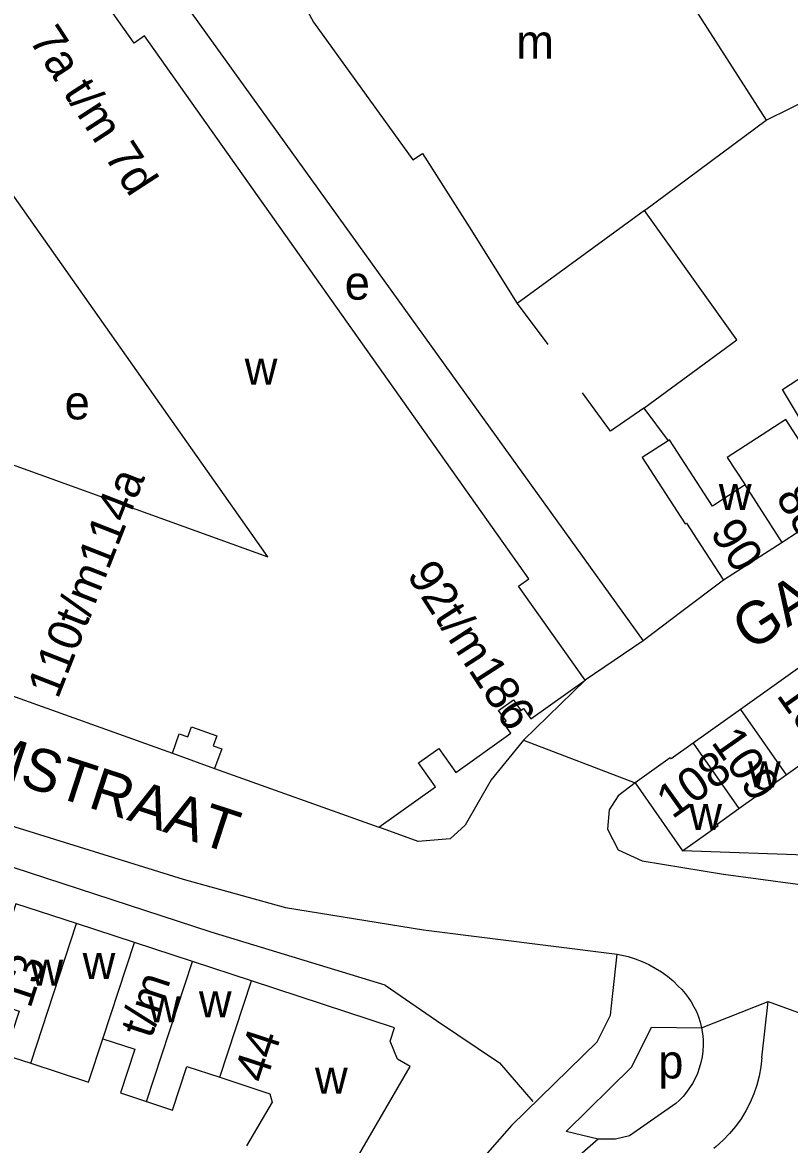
# Model space of a CAD drawing. Extents: x 159261 to 160849, y 382514 to 384534.
# Drawn here: x 160354.6 to 160445.2, y 383295.6 to 383428.1 of the extents above; entities that cross this region are included whole.
import ezdxf

# ---------------------------------------------------------------- set-up
doc = ezdxf.new("R2010")
doc.units = 0
for name, color, linetype in [('BLT_Basislijn', 7, 'Continuous'), ('BLT_Bebouwing', 7, 'Continuous'), ('BLT_Centroide', 7, 'Continuous'), ('BLT_Huisnummer', 7, 'Continuous'), ('BLT_Huisnummer_ tussenligend', 7, 'Continuous'), ('BLT_Huisnummer_reeks', 7, 'Continuous'), ('BLT_Onderverdeling_panden', 7, 'Continuous'), ('BLT_Straatnaam', 7, 'Continuous'), ('BLT_Vlakafsluiter', 7, 'Continuous')]:
    doc.layers.add(name, color=color, linetype=linetype)

msp = doc.modelspace()

# ---------------------------------------------------------------- linework, layer by layer
at = {"layer": 'BLT_Basislijn'}
for p, q in [((160442.43, 383416.62), (160448.68, 383419.71)), ((160413.05, 383394.96), (160416.66, 383390.12)), ((160427.99, 383382.6), (160430.85, 383378.73)), ((160437.39, 383362.27), (160432.31, 383358.46)), ((160432.31, 383358.46), (160427.91, 383355.12)), ((160427.91, 383355.12), (160421.05, 383350.47)), ((160421.05, 383350.47), (160413.78, 383343.38)), ((160413.78, 383343.38), (160409.96, 383338.71)), ((160372.32, 383341.84), (160377.31, 383340.05)), ((160450.78, 383329.66), (160432.57, 383330.32)), ((160424.29, 383313.1), (160424.84, 383318.1)), ((160397.45, 383314.44), (160403.49, 383310.27)), ((160441.94, 383305.89), (160442.65, 383312.51)), ((160403.49, 383310.27), (160410.93, 383305.29)), ((160410.93, 383305.29), (160414.87, 383300.71)), ((160431.78, 383300.49), (160426.31, 383296.65)), ((160422.58, 383296.25), (160418.81, 383297.19)), ((160423.44, 383296.25), (160422.58, 383296.25)), ((160424.64, 383296.25), (160423.44, 383296.25)), ((160426.31, 383296.65), (160424.64, 383296.25))]:
    msp.add_line(p, q, dxfattribs=at)
for points in [[(160368.12, 383436.27), (160369.92, 383434.89), (160372.29, 383432.48), (160427.91, 383355.12)], [(160427.99, 383382.6), (160438.96, 383390.68), (160428.06, 383405.95)], [(160427.99, 383382.6), (160424.04, 383379.89), (160420.75, 383384.41)], [(160323.65, 383342.9), (160350.12, 383334.27), (160373.6, 383326.96), (160385.68, 383323.64), (160401.99, 383321), (160424.84, 383318.1)], [(160409.96, 383338.71), (160406.88, 383333.33), (160405.11, 383331.73), (160401.35, 383331.44), (160396.69, 383333.1)], [(160426.95, 383338.34), (160424.95, 383336.83), (160423.88, 383335.16), (160423.69, 383332.86), (160424.94, 383330.43), (160427.81, 383329.12), (160437.39, 383327.56), (160480.08, 383321.82), (160483.56, 383321.62), (160489.01, 383321.3), (160500, 383319.86), (160526.04, 383316.41)], [(160397.45, 383314.44), (160376.9, 383320.73), (160353.53, 383328.34)], [(160424.84, 383318.1), (160426.15, 383317.84), (160426.98, 383317.58), (160427.79, 383317.26), (160428.58, 383316.9), (160429.34, 383316.48), (160430.08, 383316.01), (160430.78, 383315.5), (160431.44, 383314.95), (160432.05, 383314.34)], [(160412.37, 383297.88), (160422.47, 383307.78), (160424.04, 383310.93), (160424.29, 383313.1)], [(160412.37, 383297.88), (160422.47, 383307.78), (160424.04, 383310.93), (160424.29, 383313.1)], [(160432.05, 383314.34), (160432.46, 383313.93), (160432.86, 383313.48), (160433.23, 383312.99), (160433.58, 383312.47), (160433.9, 383311.91), (160434.19, 383311.33), (160434.43, 383310.71), (160434.64, 383310.07), (160434.8, 383309.41)], [(160418.81, 383297.19), (160426.57, 383304.8), (160428.91, 383309.5), (160434.8, 383309.41)], [(160434.8, 383309.41), (160434.91, 383308.73), (160434.98, 383308.05), (160434.99, 383307.36), (160434.95, 383306.67), (160434.86, 383305.99), (160434.72, 383305.32), (160434.54, 383304.66), (160434.31, 383304.03), (160434.04, 383303.42), (160433.73, 383302.85), (160433.39, 383302.31), (160433.02, 383301.8), (160432.62, 383301.32), (160432.21, 383300.89), (160431.78, 383300.49)], [(160441.94, 383305.89), (160441.81, 383304.8), (160441.61, 383303.72), (160441.33, 383302.65), (160440.98, 383301.61), (160440.54, 383300.59), (160440.04, 383299.61), (160439.47, 383298.67), (160438.83, 383297.78), (160438.12, 383296.93), (160437.36, 383296.13), (160436.54, 383295.4), (160436.26, 383295.17)], [(160412.37, 383297.88), (160399.61, 383283.34), (160385.72, 383265.78), (160373.36, 383245.57), (160365.56, 383230.35), (160357.3, 383210.46), (160353.18, 383198.31), (160349.56, 383183.84), (160347.8, 383173.48)], [(160422.58, 383296.25), (160418.15, 383292.38), (160406.69, 383280.59), (160393.26, 383264.28), (160381.77, 383247.46), (160377.4, 383239.36), (160367.53, 383217.39), (160362.84, 383202.11), (160360.83, 383194.38), (160358.71, 383182.11), (160358.07, 383180.46), (160356.76, 383178.35), (160354.57, 383175.9), (160351.57, 383174.34), (160347.8, 383173.48)]]:
    msp.add_lwpolyline(points, dxfattribs=at)
at = {"layer": 'BLT_Bebouwing'}
for p, q in [((160423.68, 383445.9), (160442.43, 383416.62)), ((160367.82, 383425.72), (160361.94, 383434.03)), ((160428.06, 383405.95), (160442.43, 383416.62)), ((160428.06, 383405.95), (160413.05, 383394.96)), ((160430.85, 383378.73), (160427.8, 383376.76)), ((160451.26, 383371.24), (160444.32, 383366.75)), ((160444.32, 383366.75), (160437.39, 383362.27)), ((160421.05, 383350.47), (160413.2, 383361.57)), ((160324.44, 383359.03), (160372.32, 383341.84)), ((160448.3, 383353.35), (160439.39, 383347)), ((160414.65, 383345.9), (160421.05, 383350.47)), ((160377.31, 383340.05), (160396.69, 383333.1)), ((160367.85, 383319.48), (160361.01, 383321.72)), ((160374.68, 383317.24), (160367.85, 383319.48)), ((160381.65, 383314.95), (160374.68, 383317.24)), ((160391.43, 383289.46), (160400.38, 383304.83))]:
    msp.add_line(p, q, dxfattribs=at)
for points in [[(160383.42, 383441.82), (160385.51, 383438.39), (160384.78, 383437.91), (160386.46, 383432.87), (160388.97, 383428.19), (160400.73, 383411.94), (160401.87, 383412.66), (160407.38, 383404.01), (160413.05, 383394.96)], [(160413.2, 383361.57), (160414.41, 383362.43), (160369.03, 383426.57), (160367.82, 383425.72)], [(160343.86, 383379.35), (160383.59, 383365.03), (160350.18, 383412.42)], [(160452.21, 383371.79), (160449.62, 383376.07), (160448.02, 383378.71), (160444.35, 383384.79), (160448.9, 383387.76)], [(160451.26, 383371.24), (160448.54, 383375.44), (160446.86, 383378.03), (160444.75, 383381.27), (160437.83, 383376.77), (160439.94, 383373.53)], [(160439.94, 383373.53), (160436.08, 383371.02), (160431.02, 383378.84), (160430.85, 383378.73)], [(160427.8, 383376.76), (160432.87, 383368.94), (160433.01, 383369.03), (160434.67, 383366.46), (160437.39, 383362.27)], [(160396.69, 383333.1), (160403.4, 383337.88), (160401.38, 383340.71), (160403.78, 383342.42), (160405.79, 383339.58), (160412.28, 383344.21), (160411.42, 383345.44), (160411.74, 383345.67), (160410.82, 383346.91), (160412.59, 383348.14), (160413.46, 383346.89), (160413.78, 383347.12), (160414.65, 383345.9)], [(160439.39, 383347), (160433.8, 383343.02)], [(160372.32, 383341.84), (160373.13, 383344.14), (160374.15, 383343.77), (160374.57, 383344.95), (160377.55, 383343.88), (160377.13, 383342.71), (160378.15, 383342.35), (160377.31, 383340.05)], [(160444.8, 383339.29), (160450.43, 383343.3), (160451.67, 383341.57), (160455, 383343.95)], [(160433.8, 383343.02), (160431.21, 383341.17), (160431.11, 383341.31), (160426.95, 383338.34)], [(160426.95, 383338.34), (160432.57, 383330.32)], [(160439.22, 383335.31), (160444.8, 383339.29)], [(160432.57, 383330.32), (160436.75, 383333.3), (160436.63, 383333.47), (160439.22, 383335.31)], [(160361.01, 383321.72), (160353.85, 383324.07), (160350.13, 383312.73), (160354.22, 383311.39), (160352.53, 383306.23), (160355.6, 383305.23)], [(160400.38, 383304.83), (160398.89, 383305.7), (160398.05, 383307.85), (160398.56, 383309.4), (160381.65, 383314.95)], [(160355.6, 383305.23), (160362.43, 383302.98), (160364.12, 383308.12)], [(160364.12, 383308.12), (160367.89, 383306.88), (160366.2, 383301.72), (160369.26, 383300.71)], [(160369.26, 383300.71), (160372.32, 383299.71), (160374.01, 383304.86), (160377.92, 383303.58)], [(160377.92, 383303.58), (160383.83, 383301.64), (160384.1, 383300.63), (160381.09, 383295.47)]]:
    msp.add_lwpolyline(points, dxfattribs=at)
at = {"layer": 'BLT_Onderverdeling_panden'}
for p, q in [((160444.32, 383366.75), (160439.94, 383373.53)), ((160439.39, 383347), (160444.8, 383339.29)), ((160433.8, 383343.02), (160439.22, 383335.31)), ((160355.6, 383305.23), (160361.01, 383321.72)), ((160364.12, 383308.12), (160367.85, 383319.48)), ((160369.26, 383300.71), (160374.68, 383317.24)), ((160377.92, 383303.58), (160381.65, 383314.95))]:
    msp.add_line(p, q, dxfattribs=at)
at = {"layer": 'BLT_Vlakafsluiter'}
for p, q in [((160413.78, 383343.38), (160426.95, 383338.34)), ((160434.8, 383309.41), (160442.65, 383312.51)), ((160442.65, 383312.51), (160453.08, 383308.75))]:
    msp.add_line(p, q, dxfattribs=at)

# ---------------------------------------------------------------- texts
at = {"layer": 'BLT_Centroide'}
for s, p in [('m', (160412.92, 383423.88)), ('e', (160392.67, 383395.41)), ('w', (160380.86, 383385.37)), ('e', (160359.6, 383381.27)), ('w', (160436.84, 383370.56)), ('w', (160440.28, 383337.82)), ('w', (160433.35, 383332.76)), ('w', (160355.56, 383314.38)), ('w', (160361.72, 383315.2)), ('w', (160369.41, 383310.06)), ('w', (160375.45, 383310.67)), ('p', (160429.69, 383303.44)), ('w', (160389.16, 383301.64))]:
    msp.add_text(s, height=4, dxfattribs=at).set_placement(p)
at = {"layer": 'BLT_Huisnummer'}
for s, rotation, p in [('90', 302.9273, (160435.72, 383367.89)), ('107', 305.1014, (160443.57, 383348.67)), ('109', 305.1014, (160435.86, 383343.14)), ('108', 35.4724, (160431.35, 383334))]:
    msp.add_text(s, height=4, rotation=rotation, dxfattribs=at).set_placement(p)
at = {"layer": 'BLT_Huisnummer_ tussenligend'}
msp.add_text('88', height=4, rotation=301.1582, dxfattribs=at).set_placement((160443.48, 383372.1))
at = {"layer": 'BLT_Huisnummer_reeks'}
for s, rotation, p in [('7a t/m 7d', 302.9273, (160355.3, 383426.1)), ('110t/m114a', 68.5687, (160358.8, 383348.15)), ('92t/m186', 302.9273, (160399.92, 383362.91)), ('13', 71.8364, (160355.54, 383311.6)), ('t/m', 71.8317, (160369.85, 383308.05)), ('44', 71.8359, (160383.32, 383302.74))]:
    msp.add_text(s, height=4, rotation=rotation, dxfattribs=at).set_placement(p)
at = {"layer": 'BLT_Straatnaam'}
for s, rotation, p in [('GAGELSTRAAT', 32.8441, (160440.57, 383353.82)), ('WILLEMSTRAAT', 341.9397, (160329.73, 383346.1))]:
    msp.add_text(s, height=5, rotation=rotation, dxfattribs=at).set_placement(p)

doc.saveas('drawing.dxf')
